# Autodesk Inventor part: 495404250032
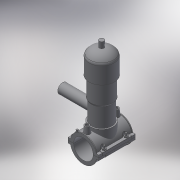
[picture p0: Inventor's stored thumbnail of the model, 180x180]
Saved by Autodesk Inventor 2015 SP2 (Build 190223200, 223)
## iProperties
Created: 2017-07
Part Number: 495404250032
Material: Generic
Description: PLASSON TAPPING VALVE 250-32
Document SubType Name: Modeling
Designer: KIM
Density: 1 g/cm^3
Appearance: Default
Author: KIM
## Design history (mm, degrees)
derived "495404-4954S4.ipt"
feature "Solid1::495404-4954S4.ipt"
feature "Solid2::495404-4954S4.ipt"
tag "TaggingFeature1"
body "Solid1"
body "Solid2"
other parameters: "d2" = 327.6, "d3" = 62.5, "d4" = 176, "d5" = 0, "d6" = 0.1, "d8" = 0, "d19" = 6, "d20" = 6, "d21" = 105.6, "d23" = 0, "d24" = 52.8, "d26" = 0, "d27" = 3, "d28" = 3, "d29" = 3, "d30" = 83.33333, "d31" = 6, "d32" = 0, "d33" = 0, "d34" = 0.6, "d40" = 152.1, "d47" = 192.25, "d70" = 15, "d72" = 0, "d73" = 6, "d75" = 5, "d76" = 0, "d77" = 12.5, "d78" = 155, "d79" = 15, "d80" = 70.4, "d82" = 5 deg, "d84" = 4, "d85" = 14, "d86" = 0, "d87" = 3, "d88" = 0, "d89" = 1, "d90" = 1, "d91" = 140.8, "d92" = 0, "d93" = 0.5, "d94" = 131.57895, "d96" = 301.275, "d97" = 3.52, "d98" = 0, "d120" = 140 deg, "d121" = 24.228, "d122" = 20 deg, "d123" = 585, "d124" = 175.5, "d126" = 0, "d143" = 257.5, "d145" = 32.69231, "d149" = 3.75, "d150" = 35.96154, "d153" = 176, "d154" = 0, "d156" = 146.25, "d157" = 160 deg, "d159" = 8.5, "d161" = 3.75, "d162" = 105.6, "d163" = 0, "d164" = 125, "d167" = 25, "d168" = 142.68293, "d170" = 3.75, "d172" = 0, "d173" = 1, "d175" = 125, "d176" = 20 deg, "d177" = 17.5, "d178" = 42.5, "d180" = 0, "d183" = 17, "d184" = 14, "d185" = 57.2, "d186" = 57.2, "d187" = 146.25, "d188" = 12.75, "d189" = 17.5, "d190" = 0, "d191" = 219.375, "d193" = 8.5, "d194" = 4.4, "d195" = 90 deg, "d197" = 0, "d199" = 0, "d205" = 14.64, "d206" = 81.33333, "d207" = 244, "d208" = 224.48, "d209" = 207.4, "d210" = 200.08, "d211" = 146.4, "d212" = 85.4, "d213" = 65.88, "d214" = 73.2, "d216" = 21.96, "d217" = 70.76, "d218" = 80.52, "d222" = 0, "d223" = 292.5, "d224" = 126, "d225" = 46, "d226" = 32, "d229" = 126, "d230" = 0, "B_" = 252, "H_" = 126, "L_" = 176, "d_t" = 6, "d_1" = 32, "H_1" = 46, "H_2" = 244, "d148" = 3.75, "d160" = 3.75, "d169" = 3.75, "d192" = 8.5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
